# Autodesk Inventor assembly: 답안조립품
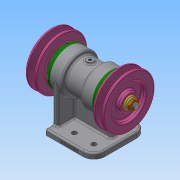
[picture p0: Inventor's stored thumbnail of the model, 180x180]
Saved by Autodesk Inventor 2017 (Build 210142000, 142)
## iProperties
Part Number: 답안조립품
Material: 일반
Document SubType Name: Assembly
Designer: 00-00
Author: 00-00
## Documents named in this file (12)
- C:\Users\00-00\Desktop\700606V1047\답안조립품.iam
- C:\Users\00-00\Desktop\700606V1047\본체.ipt
- C:\Users\00-00\Desktop\700606V1047\베어링 6204.ipt
- C:\Users\00-00\Desktop\700606V1047\축.ipt
- C:\Users\00-00\Desktop\700606V1047\커버.ipt
- C:\Users\00-00\Desktop\700606V1047\오일 실 20 32 5.ipt
- C:\Users\00-00\Desktop\700606V1047\Ű 5x5x12.ipt
- C:\Users\00-00\Desktop\700606V1047\V-벨트풀리.ipt
- C:\Users\00-00\Desktop\700606V1047\평면 와셔 10x21.ipt
- C:\Users\00-00\Desktop\700606V1047\스프링 와셔 10.ipt
- C:\Users\00-00\Desktop\700606V1047\너트 M10.ipt
- C:\Users\00-00\Desktop\700606V1047\볼트 M4.ipt
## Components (4 placed, 2 different names)
1. Ű 5x5x12:1
2. Ű 5x5x12:2
3. V-벨트풀리:1
4. V-벨트풀리:2
